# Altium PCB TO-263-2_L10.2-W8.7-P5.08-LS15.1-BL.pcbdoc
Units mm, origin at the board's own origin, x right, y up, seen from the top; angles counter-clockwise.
Board outline 23.7 x 29.94 mm, 2 copper layers (Top Layer, Bottom Layer), stack 0 mm thick; 1 components, 0 nets, 3 pads, 0 vias.
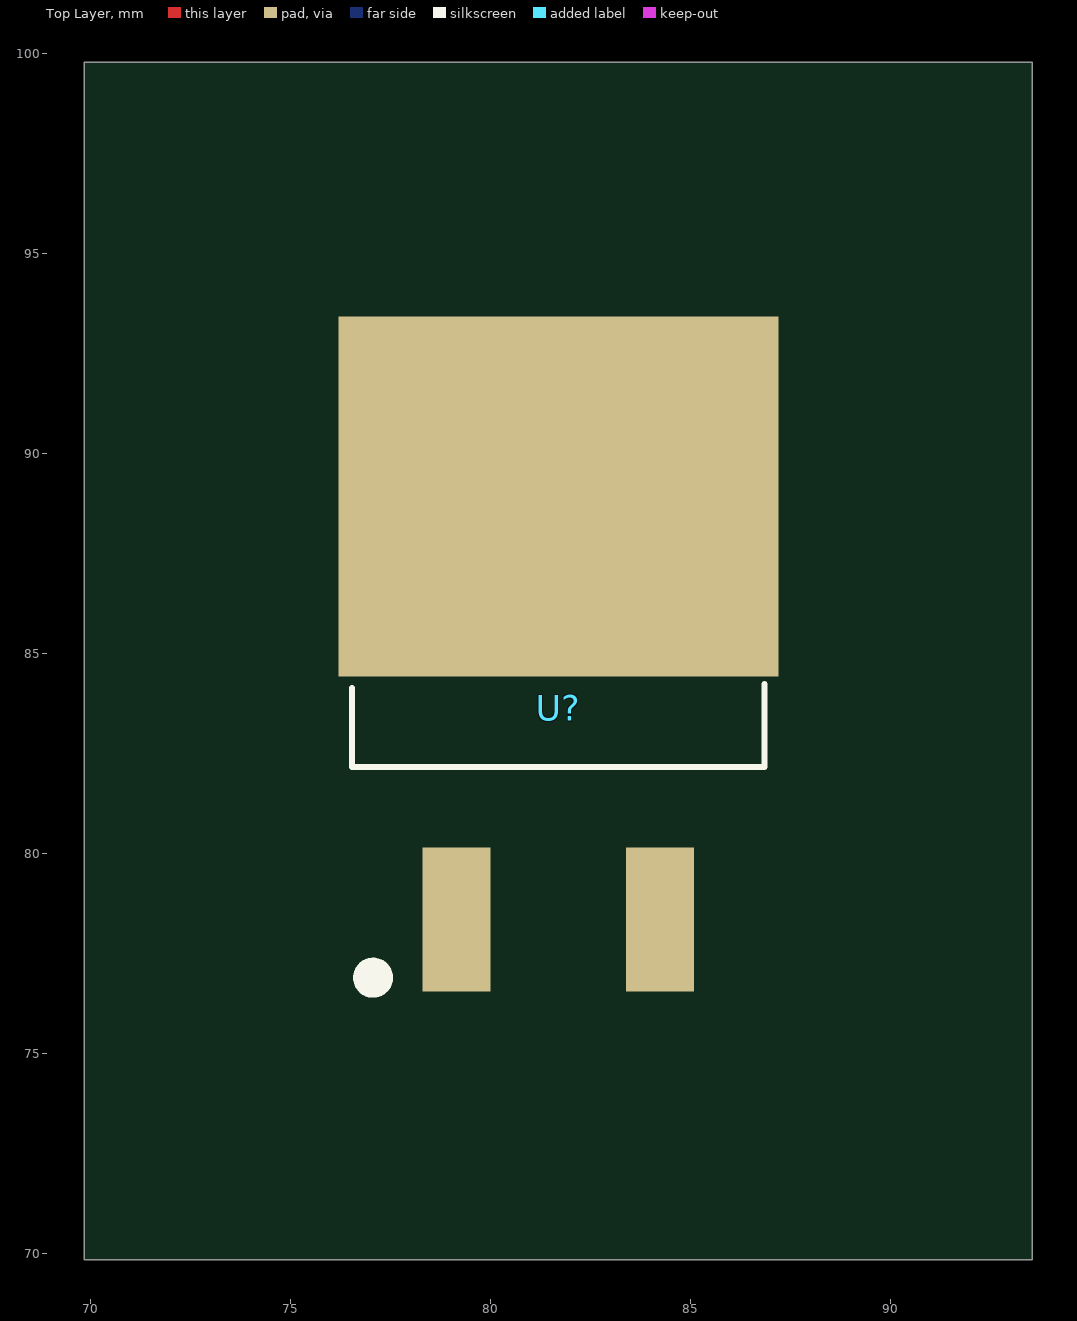
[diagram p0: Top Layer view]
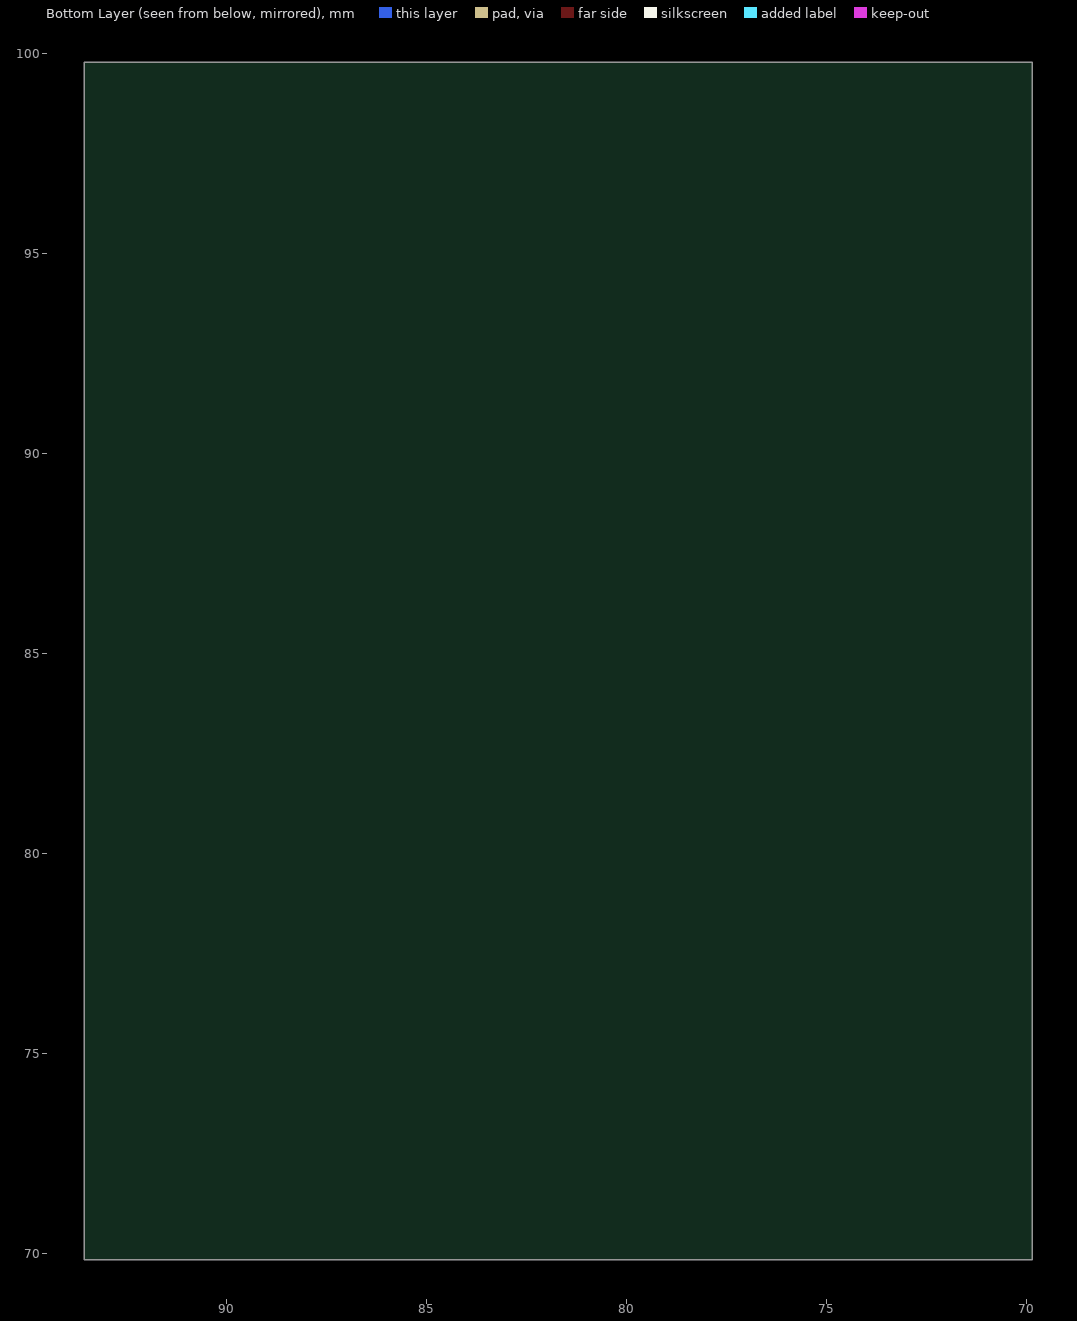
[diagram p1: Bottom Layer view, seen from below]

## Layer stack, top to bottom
Top Layer: signal copper (thickness not stored)
Bottom Layer: signal copper (thickness not stored)

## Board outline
93.55,69.85 69.85,69.85 69.85,99.793 93.55,99.793

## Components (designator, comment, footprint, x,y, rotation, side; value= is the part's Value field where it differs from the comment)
U? "" TO-263-2_L10.2-W8.7-P5.08-LS15.1-BL 81.7,83.65 r0 top

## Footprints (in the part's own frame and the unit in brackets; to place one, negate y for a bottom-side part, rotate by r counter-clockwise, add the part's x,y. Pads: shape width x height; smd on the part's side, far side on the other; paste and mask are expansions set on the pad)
TO-263-2_L10.2-W8.7-P5.08-LS15.1-BL [mm]
  rect 1.7x3.6 smd: 1(-2.54,-5.293) 3(2.54,-5.293)
  rect 11x9 smd: 2(0,5.293)
  silkscreen extent -5.16,-6.99 5.16,0.6

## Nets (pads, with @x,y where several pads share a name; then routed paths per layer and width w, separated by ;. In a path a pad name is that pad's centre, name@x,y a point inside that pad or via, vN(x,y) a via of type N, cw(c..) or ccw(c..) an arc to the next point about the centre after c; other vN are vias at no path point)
pads on no net: U?.1 U?.2 U?.3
